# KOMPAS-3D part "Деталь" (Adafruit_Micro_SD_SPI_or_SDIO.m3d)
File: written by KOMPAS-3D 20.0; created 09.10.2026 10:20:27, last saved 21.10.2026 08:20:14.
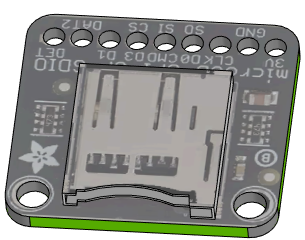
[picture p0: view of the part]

Document properties: Полное имя файла: D:\RicWork\Project-EPS32\box_compas\SD card\Adafruit_Micro_SD_SPI_or_SDIO.m3d

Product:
- Part/product: Деталь
    Масса: 0.0074136
  - Body: Тело 1
      Масса: 0.00727359

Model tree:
1. Эскиз:1
2. Элемент выдавливания:1
     Расстояние 1 = 1.5
3. Эскиз:2  (with: Элемент выдавливания:1)
4. Элемент выдавливания:2
     Расстояние 2 = 1.5
5. Эскиз:3  (with: Элемент выдавливания:1)
6. Элемент выдавливания:3
     Расстояние 2 = 1.5
7. Массив по сетке:1  (with: Элемент выдавливания:3, Эскиз:3)  (9 pattern instances)
     Шаг 1 = 10; Угол раствора = -90; Шаг 2 = 2.54
8. Скругление:1  (with: Элемент выдавливания:1)
     Радиус = 2.5
9. Эскиз:5  (with: Элемент выдавливания:1)
10. Элемент выдавливания:4
     Расстояние 1 = 1.8
11. Эскиз:7  (with: Элемент выдавливания:4)
12. Элемент выдавливания:6
     Расстояние 2 = 13

Referenced files in D:\myProjects\Progect_esp32\box_compas\: Adafruit_Micro_SD_SPI_or_SDIO.png, socket_Micro_SD_up.png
